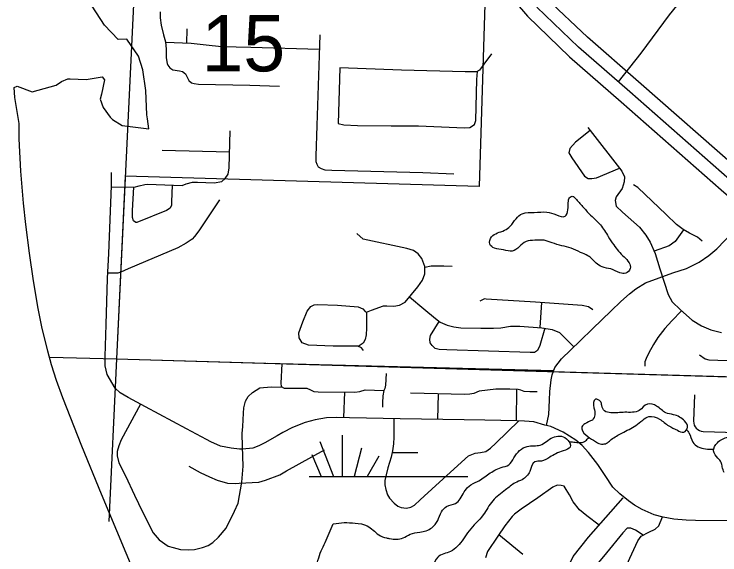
# Model space of a CAD drawing. Extents: x 1219626 to 1426462, y 456797 to 752399.
# Drawn here: x 1355119 to 1360454, y 545489 to 549577 of the extents above; entities that cross this region are included whole.
import ezdxf

# ---------------------------------------------------------------- set-up
doc = ezdxf.new("R2010")
doc.units = 0
for name, color, linetype in [('Lakes and Ponds', 7, 'Continuous'), ('Local Roads Paved', 7, 'Continuous'), ('Narrow River Creek and Branch and Slough', 7, 'Continuous'), ('Section Lines', 7, 'Continuous'), ('Section Numbers', 7, 'Continuous'), ('State Park', 7, 'Continuous'), ('State Route Divided Highway Outline and Fill', 7, 'Continuous'), ('State Routes Highway Center Lines', 7, 'Continuous'), ('Swamps', 7, 'Continuous')]:
    doc.layers.add(name, color=color, linetype=linetype)

msp = doc.modelspace()

# ---------------------------------------------------------------- linework, layer by layer
at = {"layer": 'Lakes and Ponds'}
for points in [[(1355123.3, 548947.7), (1355118.9, 549022.5), (1355143.1, 549031.3), (1355255.3, 548989.5), (1355435.7, 549040.2), (1355477.5, 549066.6), (1355526, 549088.6), (1355543.6, 549088.6), (1355603, 549086.4), (1355662.4, 549082), (1355783.4, 549104), (1355803.2, 549079.8), (1355779, 548971.9), (1355770.2, 548934.5), (1355792.2, 548870.6), (1355845, 548798), (1355862.6, 548780.4), (1355935.2, 548736.3), (1356137.7, 548709.9), (1356126.7, 548784.8), (1356122.3, 548815.6), (1356113.5, 549000.5), (1356092.2, 549155.6), (1356059.5, 549259), (1355970.4, 549387.5), (1355904.6, 549386.2), (1355801.2, 549492.9), (1355675.1, 549689.4)], [(1356082, 545225.3), (1355780.4, 545948.5), (1355632, 546311.3), (1355486.5, 546676.3), (1355438.4, 546808.4), (1355401.5, 546925.5), (1355372.8, 547029), (1355329.3, 547212), (1355301.5, 547350.6), (1355265.6, 547559.8), (1355234.4, 547770), (1355207, 547985.6), (1355190.4, 548147.5), (1355170.6, 548390.5), (1355156.2, 548633.8), (1355156.1, 548751.1), (1355123.3, 548947.7)]]:
    msp.add_lwpolyline(points, dxfattribs=at)
for points in [[(1358938.1, 547820.2), (1358884.8, 547785.6), (1358818.8, 547795.1), (1358749.7, 547807.6), (1358715.2, 547839), (1358727.7, 547892.5), (1358825.1, 547942.7), (1358869.1, 547974.1), (1358913, 548030.7), (1358960.1, 548068.4), (1359051.2, 548077.8), (1359145.4, 548081), (1359217.6, 548059), (1359283.6, 548049.5), (1359305.6, 548096.7), (1359308.7, 548165.8), (1359321.3, 548194.1), (1359337, 548200.4), (1359355.8, 548190.9)], [(1359355.8, 548190.9), (1359409.2, 548131.2), (1359465.7, 548068.4), (1359550.5, 547983.6), (1359610.2, 547895.6), (1359651, 547832.8), (1359729.5, 547741.6), (1359767.2, 547697.7), (1359776.6, 547653.7), (1359742.1, 547619.1), (1359698.1, 547622.3), (1359629, 547650.5), (1359563.1, 547666.2), (1359519.1, 547694.5), (1359456.3, 547751.1), (1359399.8, 547776.2), (1359330.7, 547807.6), (1359258.5, 547826.5), (1359186.2, 547848.5), (1359126.6, 547867.3), (1359054.3, 547867.3), (1358988.4, 547857.9), (1358938.1, 547820.2)], [(1359633.2, 546362.8), (1359713.4, 546410.3), (1359819.1, 546468.6), (1359870.2, 546508.7), (1359917.6, 546534.3), (1359997.8, 546516), (1360067, 546465), (1360132.7, 546432.1), (1360180.1, 546417.6), (1360209.2, 546454), (1360187.3, 546501.5), (1360103.5, 546548.9), (1360045.2, 546563.5), (1359975.9, 546614.5), (1359906.6, 546629.1), (1359844.6, 546581.7), (1359735.3, 546567.1), (1359629.5, 546563.5), (1359582.1, 546578.1), (1359560.3, 546618.2), (1359553, 546647.4), (1359512.9, 546665.6), (1359501.9, 546599.9), (1359509.2, 546548.9), (1359491, 546508.7)], [(1359491, 546508.7), (1359432.7, 546479.6), (1359410.8, 546457.7), (1359440, 546395.7), (1359498.3, 546355.5), (1359527.5, 546337.3), (1359571.2, 546326.4), (1359604, 546337.3), (1359633.2, 546362.8)], [(1358707.7, 546101.5), (1358799.7, 546149.9), (1358857.7, 546169.3), (1358896.4, 546222.5), (1358998.1, 546309.7), (1359094.8, 546319.4), (1359191.6, 546377.5), (1359293.3, 546367.8), (1359322.3, 546304.8), (1359269.1, 546275.8), (1359167.4, 546227.4), (1359104.5, 546198.3), (1359056.1, 546193.5), (1359017.4, 546120.9), (1358959.3, 546057.9), (1358906.1, 546033.7), (1358833.5, 545980.5), (1358736.7, 545898.1), (1358664.2, 545791.6), (1358557.7, 545670.6), (1358470.6, 545554.4), (1358417.3, 545515.7), (1358320.6, 545472.1), (1358286.7, 545399.5), (1358286.7, 545312.3), (1358320.6, 545225.2), (1358465.7, 545104.1), (1358669, 544939.5), (1358794.8, 544866.9), (1358920.6, 544852.3), (1358988.4, 544823.3), (1359085.2, 544794.2), (1359114.2, 544760.4), (1359114.2, 544716.8), (1359070.6, 544658.7), (1358998.1, 544634.5), (1358920.6, 544649), (1358809.3, 544653.8), (1358712.5, 544624.8), (1358669, 544605.4), (1358596.4, 544576.4), (1358581.9, 544624.8), (1358610.9, 544716.8), (1358572.2, 544784.6), (1358465.7, 544862), (1358422.2, 544900.8), (1358310.9, 544963.7), (1358189.9, 545046), (1358151.2, 545099.3), (1358073.8, 545191.3), (1358010.8, 545278.4), (1357923.7, 545278.4), (1357768.9, 545307.5), (1357652.7, 545370.4), (1357531.8, 545384.9), (1357410.8, 545409.1), (1357415.6, 545447.9), (1357468.9, 545583.4), (1357531.8, 545723.8)], [(1360486.3, 546111.2), (1360471.7, 546154.9), (1360464.4, 546187.8), (1360438.9, 546220.6), (1360406.1, 546275.3), (1360435.3, 546337.3), (1360515.5, 546381.1), (1360592, 546392), (1360621.2, 546392), (1360741.5, 546377.4), (1360850.9, 546351.9), (1360967.5, 546289.9), (1361022.2, 546231.5), (1361040.5, 546158.6), (1361047.8, 546071), (1361076.9, 545947), (1361113.4, 545874.1), (1361160.8, 545826.6), (1361189.9, 545793.8), (1361186.3, 545750), (1361157.1, 545753.7), (1361106.1, 545771.9), (1360993.1, 545797.5), (1360854.5, 545826.6), (1360781.6, 545837.6), (1360708.7, 545870.4), (1360683.2, 545917.8), (1360668.6, 545965.3)], [(1357531.8, 545723.8), (1357614, 545733.5), (1357696.3, 545728.7), (1357788.2, 545709.3), (1357875.3, 545641.5), (1357933.4, 545617.3), (1357957.6, 545612.5), (1358059.2, 545617.3), (1358112.5, 545646.4), (1358185.1, 545660.9), (1358277, 545694.8), (1358320.6, 545748.1), (1358349.6, 545815.8), (1358388.3, 545854.6), (1358456.1, 545878.8), (1358489.9, 545912.7), (1358557.7, 546009.5), (1358620.6, 546043.4), (1358707.7, 546101.5)]]:
    msp.add_spline(points, degree=3, dxfattribs=at)
at = {"layer": 'Local Roads Paved'}
for p, q in [((1356425.7, 549466.6), (1356422.9, 549355.9)), ((1356239.1, 548549.6), (1356747.5, 548535.3)), ((1359106.3, 547396.1), (1359091.9, 547207.9)), ((1359197.9, 546881.6), (1357031, 546937.2)), ((1358915.8, 546740.2), (1358914.8, 546503.7)), ((1357611.5, 546527.4), (1357619.3, 546719.4)), ((1358324.8, 546706.4), (1358319.8, 546513)), ((1360261.8, 546700.2), (1360255.3, 546500.1)), ((1360328, 546422.7), (1360730.2, 546410.8)), ((1357975.4, 546263), (1358171.8, 546263.9)), ((1358783.6, 545643.9), (1358964.3, 545495.8))]:
    msp.add_line(p, q, dxfattribs=at)
for points in [[(1359688.1, 549064.2), (1359859.2, 549282.4), (1360073.3, 549571.1), (1360271, 549818.2), (1360423.5, 550021.9), (1360544, 550172.8), (1360561.4, 550185.8), (1360603, 550190.1), (1360672.4, 550189.2), (1360783.3, 550176.2), (1360900.4, 550161.5), (1361129.2, 550144.1), (1361632.1, 550092.1), (1361695.3, 550096.5), (1361718.7, 550105.1), (1361736.1, 550143.3), (1361743, 550170.2)], [(1356221.9, 549594.9), (1356222.8, 549549.9), (1356231.5, 549494.4), (1356247.1, 549419.8), (1356262.7, 549367.8), (1356267.9, 549313.2), (1356268.8, 549246.4), (1356276.6, 549204), (1356280.9, 549191), (1356294.8, 549170.1), (1356319, 549156.3), (1356368.4, 549149.3), (1356392.7, 549144.1), (1356414.4, 549126.8), (1356430, 549096.5), (1356440.4, 549074.8), (1356458.6, 549058.3), (1356480.3, 549051.4), (1356511.5, 549048.8), (1356900.7, 549039.2), (1357125.8, 549032.3)], [(1357428.7, 549420.7), (1357424.4, 549264.6), (1357407, 548735.8), (1357398.4, 548502.6), (1357399.2, 548462.7), (1357406.2, 548441.9), (1357418.3, 548422.8), (1357439.1, 548409.8), (1357466.9, 548399.4), (1357520.6, 548396.8), (1358209, 548379.5), (1358442.2, 548370)], [(1357425.6, 549308.5), (1356908.5, 549323.6), (1356685.7, 549329.7), (1356570.4, 549343.5), (1356456, 549354.8), (1356263.3, 549361.4)], [(1358728.2, 549276.8), (1358668.4, 549199.6), (1358635.5, 549152.8), (1358613.8, 549140.7), (1358528.9, 549141.5), (1358046.8, 549153.7), (1357581.3, 549171.9), (1357568.3, 548749.7), (1357611.6, 548741), (1357714.8, 548735.8), (1357969.7, 548732.3), (1358176, 548731.5), (1358523.7, 548716.7), (1358563.5, 548719.3), (1358599.1, 548742.7), (1358609.5, 548773.1), (1358616.4, 549081.7), (1358620.7, 549142.4)], [(1359455.8, 548719.6), (1359711.6, 548390.1), (1359733.2, 548347.6), (1359731.5, 548308.6), (1359715, 548258.3), (1359670, 548195.1), (1359663, 548167.3), (1359670, 548125.7), (1359717.6, 548079.8), (1359845.1, 547966.2), (1359894.5, 547906.4), (1359927.4, 547854.4), (1359963.8, 547767.7), (1359999.4, 547652.4), (1360062.7, 547457.3), (1360093.9, 547401.8), (1360157.2, 547341.1), (1360244.7, 547264), (1360315.8, 547220.6), (1360386, 547190.3), (1360466.7, 547171.2)], [(1355854.2, 548270.8), (1356027.5, 548267.9), (1356064.8, 548278.3), (1356107.3, 548289.6), (1356128.1, 548291.3), (1356389.9, 548281.8), (1356419.4, 548294.8), (1356466.2, 548306), (1356504.3, 548306.9), (1356630.9, 548301.7), (1356689, 548313), (1356713.3, 548334.6), (1356735.8, 548366.7), (1356744.5, 548415.3), (1356751.4, 548694.4)], [(1359473.1, 548697.4), (1359362.2, 548610.3), (1359318.8, 548561.8), (1359311, 548528), (1359334.5, 548489.8), (1359431.5, 548352.8), (1359458.4, 548334.6), (1359486.2, 548333.8), (1359520.8, 548340.7), (1359694.7, 548411.8)], [(1360530.8, 545746), (1360269.9, 545750.3), (1360199.7, 545752.9), (1360105.2, 545759), (1360025.4, 545774.6), (1359956, 545792.8), (1359866.8, 545832.7), (1359808.7, 545865.6), (1359763.6, 545898.5), (1359698.6, 545949.7), (1359643.9, 546000.8), (1359585.9, 546088.4), (1359532.1, 546173.4), (1359461, 546264.4), (1359413.3, 546315.5), (1359365.7, 546355.4), (1359269.4, 546416.1), (1359175.8, 546459.5), (1359131.6, 546470.7), (1359047.5, 546494.1), (1358978.1, 546501.1), (1358919.2, 546503.7), (1358678.2, 546508), (1358521.3, 546509.7), (1358037.5, 546517.5), (1357655.2, 546526.2), (1357556.4, 546528.8), (1357479.2, 546526.2), (1357393.4, 546509.7), (1357319.7, 546489.8), (1357223.5, 546452.5), (1357150.6, 546415.2), (1357106.4, 546388.4), (1357013.7, 546335.5), (1356968.6, 546312.9), (1356924.4, 546296.5), (1356845.5, 546287.8), (1356822.9, 546287.8), (1356758.8, 546295.6), (1356679, 546311.2), (1356605.3, 546344.2), (1356572.4, 546360.6), (1356421.5, 546442.1), (1356112.9, 546608.6), (1355980.3, 546677.9), (1355920.5, 546714.3), (1355882.3, 546749), (1355822.5, 546852.2), (1355807.8, 546918.9), (1355806, 546989.2), (1355815.6, 547231), (1355826, 547578.7), (1355833.8, 547767.7), (1355854.6, 548279.2), (1355854.8, 548380.2)], [(1356313.2, 548284.5), (1356309.3, 548157.8), (1356308.4, 548132.6), (1356298.9, 548109.2), (1356271.1, 548093.6), (1356045.7, 548000.9), (1356037.9, 548000.9), (1356020.6, 548014.7), (1356012.8, 548039), (1356013.7, 548091.9), (1356023.7, 548267.9)], [(1360319.3, 547859.6), (1360283.7, 547889.9), (1360224.8, 547921.1), (1360176.2, 547948), (1360126, 547987), (1360047.9, 548063.3), (1359833.8, 548267), (1359801.7, 548286.1)], [(1356672.5, 548174.3), (1356514.7, 547939.3), (1356482.7, 547896.8), (1356463.6, 547875.2), (1356420.2, 547846.6), (1356355.2, 547811), (1355980.7, 547651.5), (1355924.4, 547627.2), (1355901.8, 547619.4), (1355827.6, 547618.4)], [(1359142.5, 546467.9), (1359161.1, 546551.3), (1359165.4, 546658), (1359168, 546723.9), (1359177.5, 546812.3), (1359186.2, 546850.4), (1359207, 546905.9), (1359256.4, 546970.9), (1359396.9, 547106.2), (1359491.4, 547198.1), (1359632.7, 547335.1), (1359704.6, 547405.3), (1359771.4, 547463.4), (1359819.1, 547499.8), (1359891.9, 547546.6), (1360097.4, 547621.1), (1360200.5, 547655), (1360297.6, 547702.6), (1360371.3, 547752.9), (1360432, 547802.3), (1360550.8, 547928), (1360620.1, 548003.5), (1360724.2, 548125.7)], [(1357760.1, 547033.4), (1357744.5, 547055), (1357716.8, 547066.3), (1357530.4, 547068), (1357344, 547074.1), (1357295.4, 547092.3), (1357272.9, 547130.5), (1357270.3, 547166.9), (1357300.6, 547250.1), (1357333.6, 547331.6), (1357363, 547367.1), (1357387.3, 547380.1), (1357414.2, 547382.7), (1357562.4, 547376.7), (1357719.4, 547364.5), (1357754.9, 547348.1), (1357772.2, 547328.1), (1357781.8, 547324.7), (1357820.8, 547338.5), (1357910.9, 547371.5), (1357936.1, 547372.3), (1357989.8, 547368.9), (1358031.4, 547375.8), (1358074.8, 547400.1), (1358171, 547516.2), (1358205.7, 547564.8), (1358223.9, 547614.2), (1358223.9, 547668.8), (1358201.4, 547728.6), (1358171.9, 547765.1), (1358138.1, 547789.3), (1358086.9, 547805.8), (1357758.4, 547876.9), (1357708.9, 547917.6)], [(1360178.8, 547946.6), (1360114.7, 547857.8), (1360069.6, 547826.6), (1359956.7, 547784.8)], [(1358429.4, 547668.8), (1358366.1, 547671.4), (1358309.7, 547670.6), (1358271.6, 547670.6), (1358223.9, 547661)], [(1358106.8, 547438.8), (1358215.2, 547348.9), (1358303.7, 547276.1), (1358339.2, 547249.2), (1358391.2, 547225.8), (1358441.5, 547212.8), (1358494.4, 547206.8), (1358647.8, 547203.3), (1358741.5, 547202.4), (1358798.7, 547206.8), (1358871.5, 547218), (1358940.9, 547218), (1359108.2, 547206.8), (1359187.1, 547193.7), (1359241.7, 547171.2), (1359349.8, 547060.9)], [(1359494, 547341.1), (1359461.9, 547364.5), (1359413.3, 547374.9), (1359060.5, 547399.2), (1358686, 547423.5), (1358673.8, 547424.4), (1358640, 547407)], [(1357781.8, 547324.7), (1357782.6, 547204.2), (1357780, 547153), (1357772.2, 547117.5), (1357756.6, 547088.8), (1357719.3, 547065.3)], [(1360164.9, 547334.3), (1360091.3, 547259.6), (1360036.7, 547199.8), (1359985.5, 547132.2), (1359951.7, 547079.3), (1359917, 547016.9), (1359895.4, 546973.5), (1359886.7, 546947.5), (1359886.7, 546915.5)], [(1359129.6, 547203.2), (1359093.4, 547073.2), (1359074.4, 547035.1), (1359051.8, 547020.4), (1359020.6, 547018.6), (1358389.5, 547040.3), (1358331.4, 547042), (1358302.8, 547050.7), (1358277.7, 547073.2), (1358263.8, 547093.2), (1358262.1, 547120.9), (1358265.5, 547146.9), (1358332.5, 547254.3)], [(1360299.4, 547002.2), (1360342.7, 546970.1), (1360369.6, 546963.1), (1360576.8, 546956.2)], [(1357142.2, 546934.4), (1357135.9, 546786.3), (1357136.8, 546762.9), (1357160.2, 546750.7), (1357215.7, 546749.9), (1357299.8, 546749), (1357332.7, 546749), (1357360.4, 546736.9), (1357384.7, 546723.9), (1357417.7, 546721.3), (1357693.3, 546718.7), (1357733.2, 546723.9), (1357771.4, 546736), (1357914.4, 546731.7)], [(1357931.8, 546860), (1357925.7, 546771.6), (1357921.3, 546746.4), (1357914.4, 546731.7), (1357906.6, 546691.8), (1357902.3, 546639.8), (1357903.1, 546605.1)], [(1356074.5, 546628.7), (1355928.7, 546359.8), (1355909.6, 546314.7), (1355896.6, 546270.5), (1355896.6, 546237.5), (1355909.6, 546184.6), (1355959.9, 546087.5), (1356028.4, 545941.9), (1356088.2, 545814.5), (1356170.6, 545654.9), (1356214.8, 545602.1), (1356283.3, 545556.1), (1356320.5, 545544.8), (1356377.8, 545529.2), (1356439.3, 545527.5), (1356483.5, 545530.1), (1356543.4, 545544.8), (1356585.8, 545559.6), (1356620.5, 545583.8), (1356664.7, 545623.7), (1356721.9, 545690.5), (1356785.2, 545819.7), (1356812.1, 545881.2), (1356840.7, 546038.1), (1356849.4, 546159.5), (1356844.2, 546307.7), (1356842.4, 546407.4), (1356846.8, 546458.6), (1356853.7, 546561.8), (1356856.3, 546601.6), (1356868.5, 546650.2), (1356888.4, 546686.6), (1356920.5, 546716.9), (1356975.1, 546753.3), (1357062.6, 546758.5), (1357149.9, 546756.1)], [(1359071.8, 546721.3), (1359017.2, 546722.1), (1358975.5, 546723.9), (1358948.7, 546733.4), (1358927.9, 546739.5), (1358866.3, 546742.9), (1358760.5, 546742.1), (1358697.3, 546733.4), (1358633.1, 546727.3), (1358593.2, 546710), (1358562.9, 546703.1), (1358524.7, 546702.2), (1358116.4, 546710.9)], [(1357989.2, 546518.6), (1357990.3, 546427.4), (1357989.4, 546378.4), (1357987.7, 546327.6), (1357978.2, 546276), (1357967.9, 546227.8), (1357944.7, 546146.9), (1357930.1, 546095.3), (1357920.6, 546051.4), (1357920.6, 546019.6), (1357927.5, 545983.5), (1357941.2, 545943.9), (1357957.6, 545917.2), (1357992, 545879.4), (1358020.4, 545858.7), (1358045.3, 545848.4), (1358084.9, 545841.5), (1358118.5, 545849.3), (1358144.3, 545864.7), (1358188.2, 545904.3), (1358306.9, 546014.4), (1358553.8, 546239), (1358603.7, 546257.1), (1358644.1, 546262.2), (1358685.4, 546271.7), (1358720.7, 546294.9), (1358761.1, 546333.6), (1358933.2, 546503)], [(1356440.2, 546161.2), (1356525.1, 546112.7), (1356595.4, 546079.7), (1356654.3, 546053.7), (1356732.3, 546030.3), (1356789.6, 546028.6), (1356820.8, 546030.3), (1356969.9, 546039.9), (1357020.2, 546052.9), (1357127.7, 546093.6), (1357177.9, 546123.9), (1357464.9, 546282.6)], [(1359541.1, 545714.7), (1359448.7, 545784.3), (1359391.5, 545831.1), (1359345.5, 545889.2), (1359316, 545942.1), (1359291.8, 545984.6), (1359276.2, 546008), (1359254.5, 546014.9), (1359223.3, 546017.5), (1359191.2, 546001.9), (1359077.6, 545919.6), (1358951.9, 545833.7), (1358901.6, 545798.2), (1358882.6, 545779.1), (1358827.1, 545708), (1358774.2, 545630), (1358697, 545513.8), (1358682.3, 545467)], [(1360534.9, 543637.4), (1360450.9, 543714.5), (1359988.8, 544174), (1359792, 544365.6), (1359553.6, 544622.2), (1359468.6, 544733.2), (1359388, 544849.3), (1359328.2, 544958.6), (1359288.3, 545060.9), (1359271, 545173.6), (1359276.2, 545261.1), (1359297.8, 545379), (1359345.5, 545476.1), (1359460.8, 545624.4), (1359723.5, 545920)], [(1359460.4, 544745), (1359572.6, 544867.1), (1359648.1, 544984.1), (1359670.6, 545034.4), (1359669.7, 545087.3), (1359667.1, 545114.2), (1359662.8, 545158.4), (1359680.1, 545224.3), (1359710.5, 545323.1), (1359772.9, 545463.6), (1359832.7, 545594.5), (1359859.6, 545630), (1359917.7, 545661.2), (1359963.6, 545683.8), (1359993.1, 545709.8), (1360019.2, 545776.2)], [(1359873.4, 545637.4), (1359816.3, 545675.1), (1359780.7, 545692.4), (1359753, 545692.4), (1359720, 545656.9), (1359596.9, 545505.2), (1359537.1, 545432.4), (1359499, 545383.8), (1359474.7, 545343.1), (1359454.7, 545282.4), (1359446.9, 545243.4), (1359443.5, 545203.5), (1359445.2, 545159.3), (1359453.9, 545117.7), (1359466, 545074.3), (1359505, 544996.3), (1359580.3, 544879)]]:
    msp.add_lwpolyline(points, dxfattribs=at)
msp.add_arc((1360330.2, 546497.6), 75, 178.1395, 268.3145, dxfattribs=at)
at = {"layer": 'Narrow River Creek and Branch and Slough'}
for points in [[(1360201.2, 546435.5), (1360219.9, 546411.5), (1360249, 546341.7), (1360289.6, 546306.9), (1360404.4, 546288.3)], [(1359317.6, 546344.2), (1359360.9, 546341.5), (1359403.7, 546338.4), (1359437.3, 546350.7), (1359464.6, 546377.9)]]:
    msp.add_spline(points, degree=3, dxfattribs=at)
at = {"layer": 'Section Lines'}
for p, q in [((1356118.8, 551727), (1355893.4, 546972.1)), ((1355389.8, 546983.1), (1355893.4, 546972.1)), ((1355893.4, 546972.1), (1355834, 545740.9)), ((1355893.4, 546972.1), (1361296.2, 546813.7))]:
    msp.add_line(p, q, dxfattribs=at)
at = {"layer": 'State Park'}
for p, q in [((1358675.8, 549653.3), (1358635.3, 548273.1)), ((1355958.2, 548351.6), (1355893.4, 546972.1)), ((1358635.3, 548273.1), (1355958.2, 548351.6))]:
    msp.add_line(p, q, dxfattribs=at)
msp.add_lwpolyline([(1355893.4, 546972.1), (1361296.2, 546813.7), (1363994.4, 546724.8)], dxfattribs=at)
at = {"layer": 'State Route Divided Highway Outline and Fill'}
for points in [[(1358658.1, 549961.1), (1358998.4, 549560.4), (1359317.9, 549254.7), (1359706.6, 548915.2), (1360464.5, 548249.2), (1361358.7, 547480.4), (1362247.2, 546733.7), (1362720.6, 546315.6), (1363146.2, 545949.6), (1363413.8, 545723.6), (1364110.6, 545108.2), (1364949.7, 544386), (1365882.6, 543567.9), (1366132.9, 543352), (1366461.6, 543061)], [(1366594.2, 543210.8), (1366264.5, 543502.6), (1366013.9, 543718.8), (1365080.9, 544536.9), (1364242, 545259), (1363544.6, 545875), (1363275.9, 546101.8), (1362852, 546466.3), (1362377.8, 546885.2), (1361488.2, 547632.8), (1360595.8, 548400.1), (1359838.4, 549065.6), (1359452.9, 549402.4), (1359144.1, 549697.7)]]:
    msp.add_lwpolyline(points, dxfattribs=at)
at = {"layer": 'State Routes Highway Center Lines'}
msp.add_lwpolyline([(1366527.9, 543135.9), (1366198.7, 543427.3), (1365948.2, 543643.3), (1365015.3, 544461.4), (1364176.3, 545183.6), (1363479.2, 545799.3), (1363211, 546025.7), (1362786.3, 546391), (1362312.5, 546809.4), (1361423.4, 547556.6), (1360530.1, 548324.6), (1359772.5, 548990.4), (1359385.4, 549328.5), (1359071.3, 549629.1)], dxfattribs=at)
at = {"layer": 'Swamps'}
for p, q in [((1357598.7, 546393.8), (1357598.7, 546082.8)), ((1357429.5, 546345.5), (1357532.5, 546082.8)), ((1357369.1, 546248.8), (1357439.9, 546082.8)), ((1357743.6, 546297.2), (1357690, 546082.7)), ((1357876.6, 546236.8), (1357786.8, 546083)), ((1357350, 546082.8), (1358549.8, 546082.8))]:
    msp.add_line(p, q, dxfattribs=at)

# ---------------------------------------------------------------- texts
at = {"layer": 'Section Numbers'}
msp.add_text('15', height=425, rotation=359.9997, dxfattribs=at).set_placement((1356535.4, 549144.3))

doc.saveas('drawing.dxf')
